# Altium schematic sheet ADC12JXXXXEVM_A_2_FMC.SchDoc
size 558 x 431 mm; Date: Not shown in title block; ApprovedBy: Not shown in title block; CheckedBy: Not shown in title block; Author: Not shown in title block; CompanyName: Not shown in title block; Engineer: Not shown in title block; Organization: Not shown in title block; Address1: Not shown in title block; Address2: Not shown in title block; Address3: Not shown in title block; Address4: Not shown in title block; DocumentNumber: 2; Revision: Use project parameter SCH_Rev; SheetNumber: 2; SheetTotal: 7; PageSetup: Record=PageOptions|CenterHorizontal=True|CenterVertical=True|PrintScale=0.62|XCorrection=1.00|YCorrection=1.00|PrintKind=0|BorderSize=5000000|LeftOffset=0|BottomOffset=0|Orientation=2|PaperLength=1000|PaperWidth=1000|Scale=100|PaperSource=15|PrintQuality=600|MediaType=1|DitherType=10|PaperKind=11x17|PrintScaleMode=1
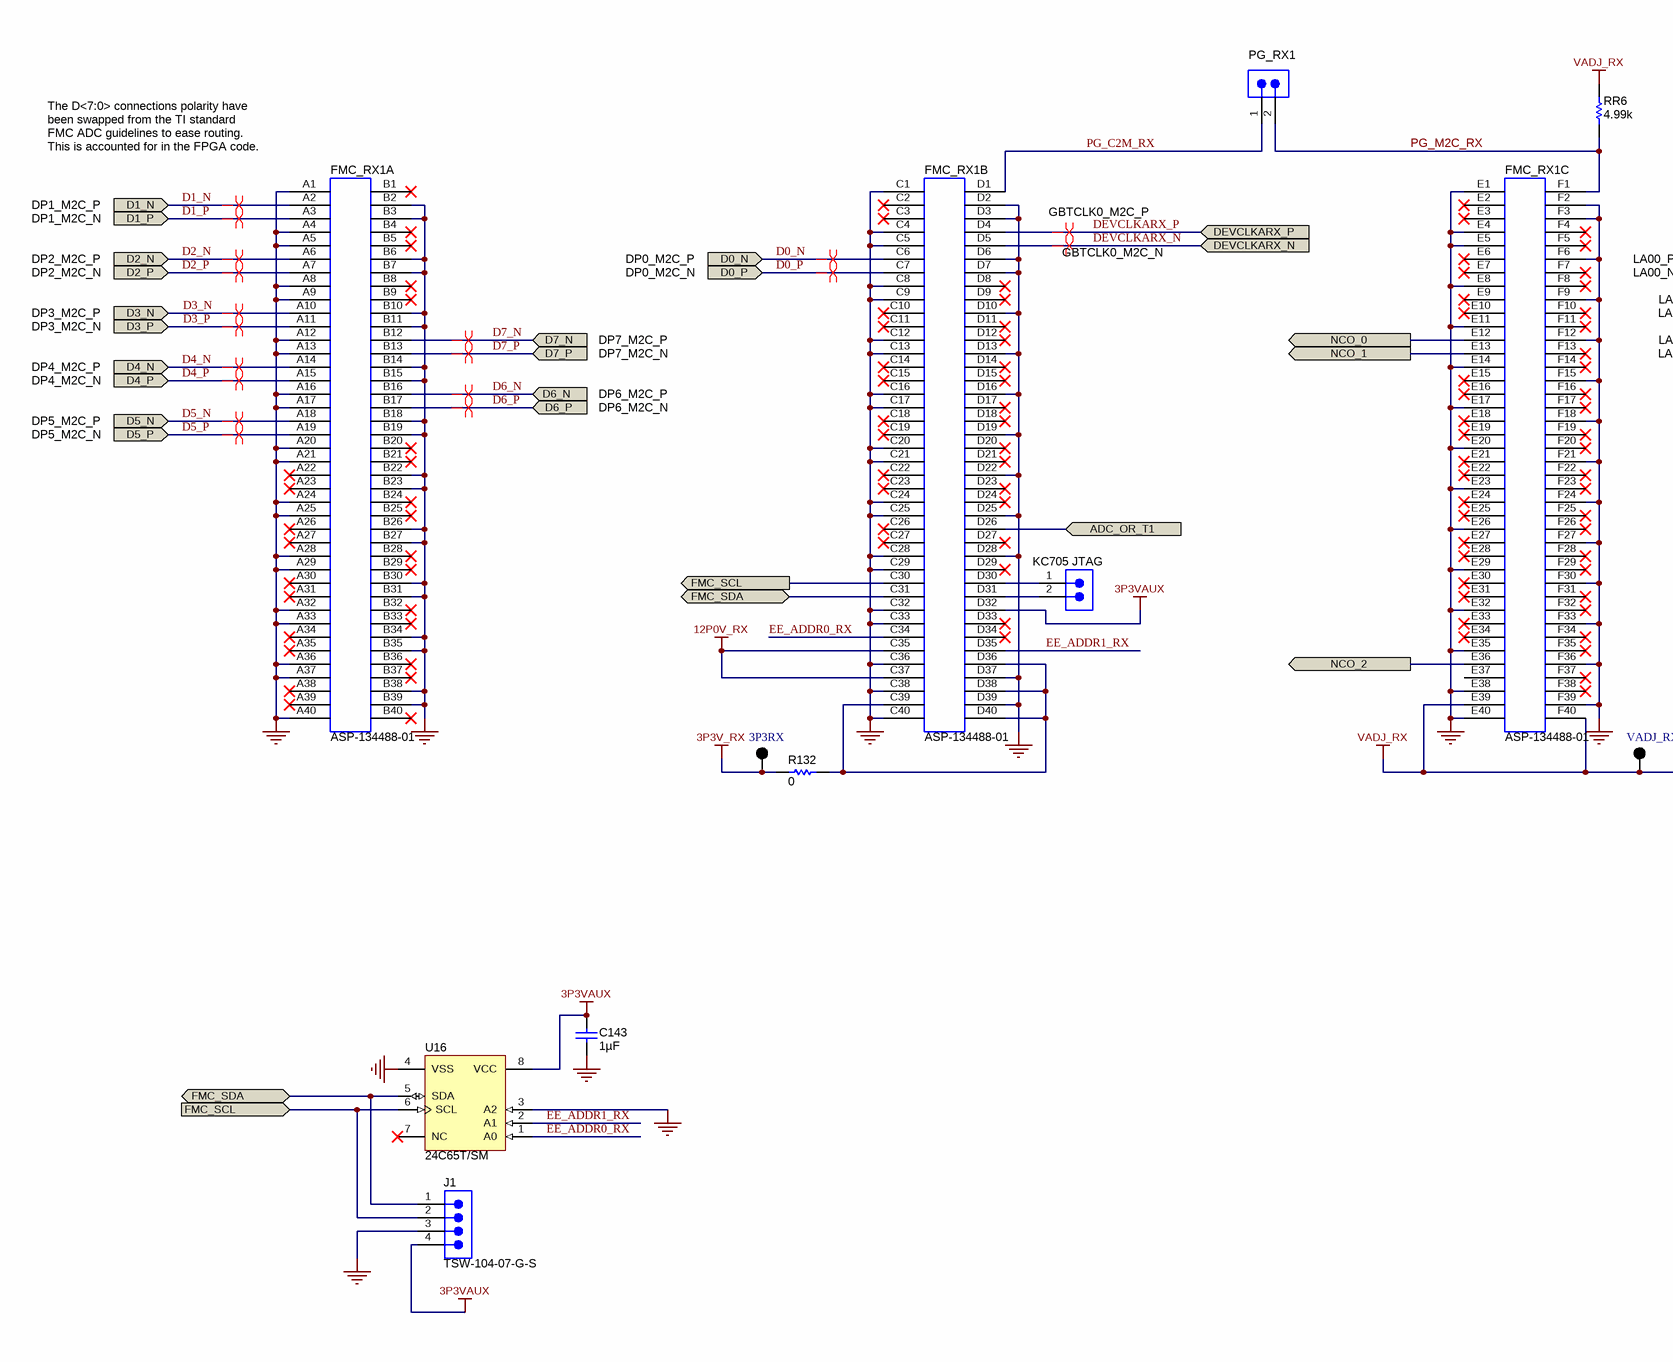
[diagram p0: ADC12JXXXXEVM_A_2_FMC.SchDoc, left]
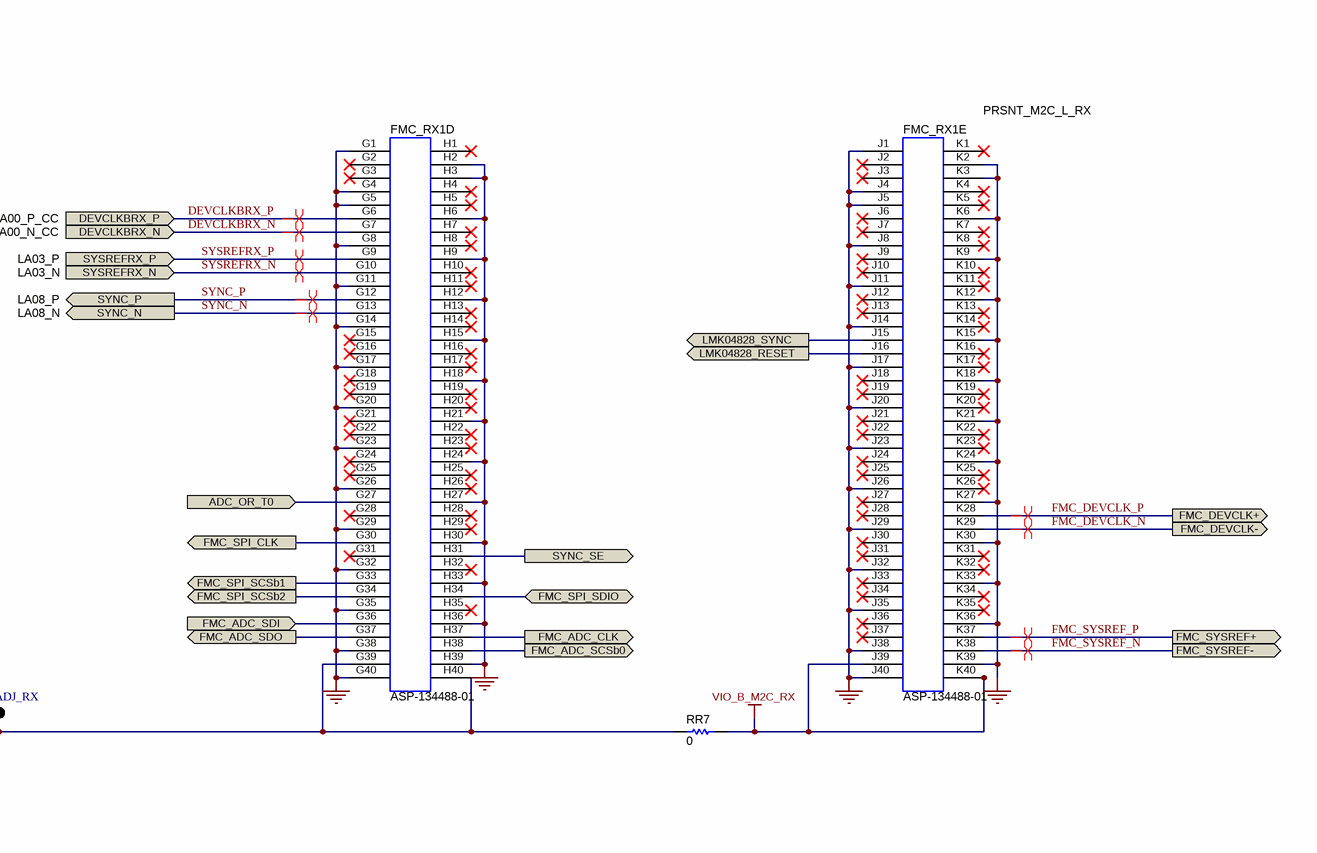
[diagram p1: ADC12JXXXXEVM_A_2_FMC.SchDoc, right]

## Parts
3P3RX  5011  [Keystone5011]  (value not drawn)
C143  ValueDisplayed: 1µF  [0603L]  (hidden comment: C1608X5R1A105K)
FMC_RX1  ASP-134488-01  [CONN_SEARAY_ASP-134488-01]  (parts A,B,C,D,E of 5)
J1  TSW-104-07-G-S  [TSW-104-07-G-S]
KC705_JTAG  TSW-102-07-G-S  [TSW-102-07-G-S]  (value not drawn)
PG_RX1  TSW-102-07-G-S  [TSW-102-07-G-S]  (value not drawn)
R132  value 0  [0603L]  (hidden comment: CRCW06030000Z0EA)
RR6  value 4.99k  [0603L]  (hidden comment: CRCW06034K99FKEA)
RR7  value 0  [0603L]  (hidden comment: ERJ-3GEY0R00V)
U16  24C65T/SM  [SOIJ-SM8_N]
VADJ_RX  5011  [Keystone5011]  (value not drawn)

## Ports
ADC_OR_T0 (in), ADC_OR_T1 (in), D0_N (in), D0_P (in), D1_N (in), D1_P (in), D2_N (in), D2_P (in), D3_N (in), D3_P (in), D4_N (in), D4_P (in), D5_N (in), D5_P (in), D6_N (in), D6_P (in), D7_N (in), D7_P (in), DEVCLKARX_N (in), DEVCLKARX_P (in), DEVCLKBRX_N (in), DEVCLKBRX_P (in), FMC_ADC_CLK (out), FMC_ADC_SCSb0 (out), FMC_ADC_SDI (in), FMC_ADC_SDO (out), FMC_DEVCLK+ (out), FMC_DEVCLK- (out), FMC_SCL (in), FMC_SCL (out), FMC_SDA (bidir), FMC_SPI_CLK (out), FMC_SPI_SCSb1 (out), FMC_SPI_SCSb2 (out), FMC_SPI_SDIO (bidir), FMC_SYSREF+, FMC_SYSREF-, LMK04828_RESET (out), LMK04828_SYNC (out), NCO_0 (out), NCO_1 (out), NCO_2 (out), SYNC_N (out), SYNC_P (out), SYNC_SE (out), SYSREFRX_N (in), SYSREFRX_P (in)

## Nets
3P3V_RX: 3P3RX.1 R132.1
3P3VAUX: C143.1 FMC_RX1.D32 J1.4 U16.8(VCC)
12P0V_RX: FMC_RX1.C35 FMC_RX1.C37
GND: C143.2 FMC_RX1.A1 FMC_RX1.A4 FMC_RX1.A5 FMC_RX1.A8 FMC_RX1.A9 FMC_RX1.A12 FMC_RX1.A13 FMC_RX1.A16 FMC_RX1.A17 FMC_RX1.A20 FMC_RX1.A21 FMC_RX1.A24 FMC_RX1.A25 FMC_RX1.A28 FMC_RX1.A29 FMC_RX1.A32 FMC_RX1.A33 FMC_RX1.A36 FMC_RX1.A37 FMC_RX1.A40 FMC_RX1.B2 FMC_RX1.B3 FMC_RX1.B6 FMC_RX1.B7 FMC_RX1.B10 FMC_RX1.B11 FMC_RX1.B14 FMC_RX1.B15 FMC_RX1.B18 FMC_RX1.B19 FMC_RX1.B22 FMC_RX1.B23 FMC_RX1.B26 FMC_RX1.B27 FMC_RX1.B30 FMC_RX1.B31 FMC_RX1.B34 FMC_RX1.B35 FMC_RX1.B38 FMC_RX1.B39 FMC_RX1.C1 FMC_RX1.C4 FMC_RX1.C5 FMC_RX1.C8 FMC_RX1.C9 FMC_RX1.C12 FMC_RX1.C13 FMC_RX1.C16 FMC_RX1.C17 FMC_RX1.C20 FMC_RX1.C21 FMC_RX1.C24 FMC_RX1.C25 FMC_RX1.C28 FMC_RX1.C29 FMC_RX1.C32 FMC_RX1.C33 FMC_RX1.C36 FMC_RX1.C38 FMC_RX1.C40 FMC_RX1.D2 FMC_RX1.D3 FMC_RX1.D6 FMC_RX1.D7 FMC_RX1.D10 FMC_RX1.D13 FMC_RX1.D16 FMC_RX1.D19 FMC_RX1.D22 FMC_RX1.D25 FMC_RX1.D28 FMC_RX1.D37 FMC_RX1.D39 FMC_RX1.E1 FMC_RX1.E4 FMC_RX1.E5 FMC_RX1.E8 FMC_RX1.E11 FMC_RX1.E14 FMC_RX1.E17 FMC_RX1.E20 FMC_RX1.E23 FMC_RX1.E26 FMC_RX1.E29 FMC_RX1.E32 FMC_RX1.E35 FMC_RX1.E38 FMC_RX1.E40 FMC_RX1.F2 FMC_RX1.F3 FMC_RX1.F6 FMC_RX1.F9 FMC_RX1.F12 FMC_RX1.F15 FMC_RX1.F18 FMC_RX1.F21 FMC_RX1.F24 FMC_RX1.F27 FMC_RX1.F30 FMC_RX1.F33 FMC_RX1.F36 FMC_RX1.F39 FMC_RX1.G1 FMC_RX1.G4 FMC_RX1.G5 FMC_RX1.G8 FMC_RX1.G11 FMC_RX1.G14 FMC_RX1.G17 FMC_RX1.G20 FMC_RX1.G23 FMC_RX1.G26 FMC_RX1.G29 FMC_RX1.G32 FMC_RX1.G35 FMC_RX1.G38 FMC_RX1.G40 FMC_RX1.H2 FMC_RX1.H3 FMC_RX1.H6 FMC_RX1.H9 FMC_RX1.H12 FMC_RX1.H15 FMC_RX1.H18 FMC_RX1.H21 FMC_RX1.H24 FMC_RX1.H27 FMC_RX1.H30 FMC_RX1.H33 FMC_RX1.H36 FMC_RX1.H39 FMC_RX1.J1 FMC_RX1.J4 FMC_RX1.J5 FMC_RX1.J8 FMC_RX1.J11 FMC_RX1.J14 FMC_RX1.J17 FMC_RX1.J20 FMC_RX1.J23 FMC_RX1.J26 FMC_RX1.J29 FMC_RX1.J32 FMC_RX1.J35 FMC_RX1.J38 FMC_RX1.J40 FMC_RX1.K2 FMC_RX1.K3 FMC_RX1.K6 FMC_RX1.K9 FMC_RX1.K12 FMC_RX1.K15 FMC_RX1.K18 FMC_RX1.K21 FMC_RX1.K24 FMC_RX1.K27 FMC_RX1.K30 FMC_RX1.K33 FMC_RX1.K36 FMC_RX1.K39 J1.3 U16.3(A2) U16.4(VSS)
VADJ_RX: FMC_RX1.E39 FMC_RX1.F40 FMC_RX1.G39 FMC_RX1.H40 RR6.2 RR7.1 VADJ_RX.1
VIO_B_M2C_RX: FMC_RX1.J39 FMC_RX1.K40 RR7.2
ADC_OR_T0: FMC_RX1.G27 ; port ADC_OR_T0
ADC_OR_T1: FMC_RX1.D26 ; port ADC_OR_T1
D0_N: FMC_RX1.C6 ; port D0_N
D0_P: FMC_RX1.C7 ; port D0_P
D1_N: FMC_RX1.A2 ; port D1_N
D1_P: FMC_RX1.A3 ; port D1_P
D2_N: FMC_RX1.A6 ; port D2_N
D2_P: FMC_RX1.A7 ; port D2_P
D3_N: FMC_RX1.A10 ; port D3_N
D3_P: FMC_RX1.A11 ; port D3_P
D4_N: FMC_RX1.A14 ; port D4_N
D4_P: FMC_RX1.A15 ; port D4_P
D5_N: FMC_RX1.A18 ; port D5_N
D5_P: FMC_RX1.A19 ; port D5_P
D6_N: FMC_RX1.B16 ; port D6_N
D6_P: FMC_RX1.B17 ; port D6_P
D7_N: FMC_RX1.B12 ; port D7_N
D7_P: FMC_RX1.B13 ; port D7_P
DEVCLKARX_N: FMC_RX1.D5 ; port DEVCLKARX_N
DEVCLKARX_P: FMC_RX1.D4 ; port DEVCLKARX_P
DEVCLKBRX_N: FMC_RX1.G7 ; port DEVCLKBRX_N
DEVCLKBRX_P: FMC_RX1.G6 ; port DEVCLKBRX_P
EE_ADDR0_RX: FMC_RX1.C34 U16.1(A0)
EE_ADDR1_RX: FMC_RX1.D35 U16.2(A1)
FMC_ADC_CLK: FMC_RX1.H37 ; port FMC_ADC_CLK
FMC_ADC_SCSb0: FMC_RX1.H38 ; port FMC_ADC_SCSb0
FMC_ADC_SDI: FMC_RX1.G36 ; port FMC_ADC_SDI
FMC_ADC_SDO: FMC_RX1.G37 ; port FMC_ADC_SDO
FMC_DEVCLK_N: FMC_RX1.K29 ; port FMC_DEVCLK-
FMC_DEVCLK_P: FMC_RX1.K28 ; port FMC_DEVCLK+
FMC_SCL: FMC_RX1.C30 J1.2 U16.6(SCL) ; port FMC_SCL
FMC_SDA: FMC_RX1.C31 J1.1 U16.5(SDA) ; port FMC_SDA
FMC_SPI_CLK: FMC_RX1.G30 ; port FMC_SPI_CLK
FMC_SPI_SCSb1: FMC_RX1.G33 ; port FMC_SPI_SCSb1
FMC_SPI_SCSb2: FMC_RX1.G34 ; port FMC_SPI_SCSb2
FMC_SPI_SDIO: FMC_RX1.H34 ; port FMC_SPI_SDIO
FMC_SYSREF_N: FMC_RX1.K38 ; port FMC_SYSREF-
FMC_SYSREF_P: FMC_RX1.K37 ; port FMC_SYSREF+
LMK04828_RESET: FMC_RX1.J16 ; port LMK04828_RESET
LMK04828_SYNC: FMC_RX1.J15 ; port LMK04828_SYNC
NCO_0: FMC_RX1.E12 ; port NCO_0
NCO_1: FMC_RX1.E13 ; port NCO_1
NCO_2: FMC_RX1.E36 ; port NCO_2
PG_C2M_RX: FMC_RX1.D1 PG_RX1.1
PG_M2C_RX: FMC_RX1.F1 PG_RX1.2 RR6.1
SYNC_N: FMC_RX1.G13 ; port SYNC_N
SYNC_P: FMC_RX1.G12 ; port SYNC_P
SYNC_SE: FMC_RX1.H31 ; port SYNC_SE
SYSREFRX_N: FMC_RX1.G10 ; port SYSREFRX_N
SYSREFRX_P: FMC_RX1.G9 ; port SYSREFRX_P
NetFMC_RX1_C39: FMC_RX1.C39 FMC_RX1.D36 FMC_RX1.D38 FMC_RX1.D40 R132.2
NetFMC_RX1_D30: FMC_RX1.D30 KC705_JTAG.1
NetFMC_RX1_D31: FMC_RX1.D31 KC705_JTAG.2

Not connected (* = marked no-connect by the designer): FMC_RX1 A22* A23* A26* A27* A30* A31* A34* A35* A38* A39* B1* B4* B5* B8* B9* B20* B21* B24* B25* B28* B29* B32* B33* B36* B37* B40* C2* C3* C10* C11* C14* C15* C18* C19* C22* C23* C26* C27* D8* D9* D11* D12* D14* D15* D17* D18* D20* D21* D23* D24* D27* D29* D33* D34* E2* E3* E6* E7* E9* E10* E15* E16* E18* E19* E21* E22* E24* E25* E27* E28* E30* E31* E33* E34* E37 F4* F5* F7* F8* F10* F11* F13* F14* F16* F17* F19* F20* F22* F23* F25* F26* F28* F29* F31* F32* F34* F35* F37* F38* G2* G3* G15* G16* G18* G19* G21* G22* G24* G25* G28* G31* H1* H4* H5* H7* H8* H10* H11* H13* H14* H16* H17* H19* H20* H22* H23* H25* H26* H28* H29* H32* H35* J2* J3* J6* J7* J9* J10* J12* J13* J18* J19* J21* J22* J24* J25* J27* J28* J30* J31* J33* J34* J36* J37* K1* K4* K5* K7* K8* K10* K11* K13* K14* K16* K17* K19* K20* K22* K23* K25* K26* K31* K32* K34* K35*; U16 7(NC)*

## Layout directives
differential pair: D0_N, D0_P, D1_N, D1_P, D2_N, D2_P, D3_N, D3_P, D4_N, D4_P, D5_N, D5_P, D6_N, D6_P, D7_N, D7_P, DEVCLKARX_N, DEVCLKARX_P, DEVCLKBRX_N, DEVCLKBRX_P, FMC_DEVCLK_N, FMC_DEVCLK_P, FMC_SYSREF_N, FMC_SYSREF_P, SYNC_N, SYNC_P, SYSREFRX_N, SYSREFRX_P

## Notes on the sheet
- The D<7:0> connections polarity have been swapped from the TI standard FMC ADC guidelines to ease routing.  This is accounted for in the FPGA code.
- PRSNT_M2C_L_RX
- DP1_M2C_P
- DP1_M2C_N
- GBTCLK0_M2C_P
- DP2_M2C_P
- DP2_M2C_N
- DP0_M2C_P
- DP0_M2C_N
- GBTCLK0_M2C_N
- LA00_P_CC
- LA00_N_CC
- DP3_M2C_P
- DP3_M2C_N
- DP7_M2C_P
- DP7_M2C_N
- LA03_P
- LA03_N
- LA08_P
- LA08_N
- DP4_M2C_P
- DP4_M2C_N
- DP5_M2C_P
- DP6_M2C_P
- DP6_M2C_N
- DP5_M2C_N

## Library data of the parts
3P3RX VADJ_RX = 5011: Test Point, TH, Multipurpose, Black; Manufacturer: Keystone Electronics; CompType: Test Point Loop
C143 = C1608X5R1A105K: CAP, CERM, 1uF, 10V, +/-10%, X5R, 0603; Manufacturer: TDK; Polarized: N; CompType: Capacitor; U/M: EA; Cap_F: 0.000001; Tolerance_%: 10; ESR_Ohm: 0.0057; Value1: 0.0057 ohm; TaMin_C: -55; TaMax_C: 85; Cap_Case: 0603
FMC_RX1 = ASP-134488-01: Connector, Receptacle, 400-Pos (40x10), 50x50-mil Pitch, SMT; Manufacturer: Molex; Alternate PartNumber: 45970-4315; SymbolCreator: a0799721; U/M: EA
J1 = TSW-104-07-G-S: Header, TH, 100mil, 4x1, Gold plated, 230 mil above insulator; Manufacturer: Samtec, Inc.; SymbolCreator: a0412235; U/M: EA
KC705_JTAG PG_RX1 = TSW-102-07-G-S: Header, TH, 100mil, 2x1, Gold plated, 230 mil above insulator; Manufacturer: Samtec, Inc.; U/M: EA
R132 = CRCW06030000Z0EA: RES, 0 ohm, 5%, 0.1W, 0603; Manufacturer: Vishay-Dale; Alternate Manufacturer: Any; Alternate PartNumber: Equivalent; CompType: Resistor; Value_Code: 0000; Tolerance_%: 5; Power_W: 0.1; VDC_V: 75; TempCo: 200 ppm/C; EIA_Code: E24; U/M: EA
RR6 = CRCW06034K99FKEA: RES, 4.99k ohm, 1%, 0.1W, 0603; Manufacturer: Vishay-Dale; CompType: Resistor; Res_ohm: 4990; Value_Code: 4k99; Tolerance_%: 1; Power_W: 0.1; VDC_V: 75; TempCo: 100 ppm/C; EIA_Code: E96; U/M: EA
RR7 = ERJ-3GEY0R00V: RES, 0 ohm, 5%, 0.1W, 0603; Manufacturer: Panasonic; CompType: Resistor; Value_Code: 0000; Tolerance_%: 5; Power_W: 0.1; VDC_V: 50; TempCo: 600 ppm/C; EIA_Code: E24; U/M: EA
U16 = 24C65T/SM: 64Kbit, 400kHz, 4.5V, I2C Serial EEPROM, 8-Pin SOIC 208mil, Commercial Temperature, Tape and Reel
